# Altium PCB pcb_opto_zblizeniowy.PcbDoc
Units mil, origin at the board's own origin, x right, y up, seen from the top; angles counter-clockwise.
Board outline 2160 x 480 mil, 2 copper layers (Top Layer, Bottom Layer); 11 components, 8 nets, 34 pads, 0 vias.
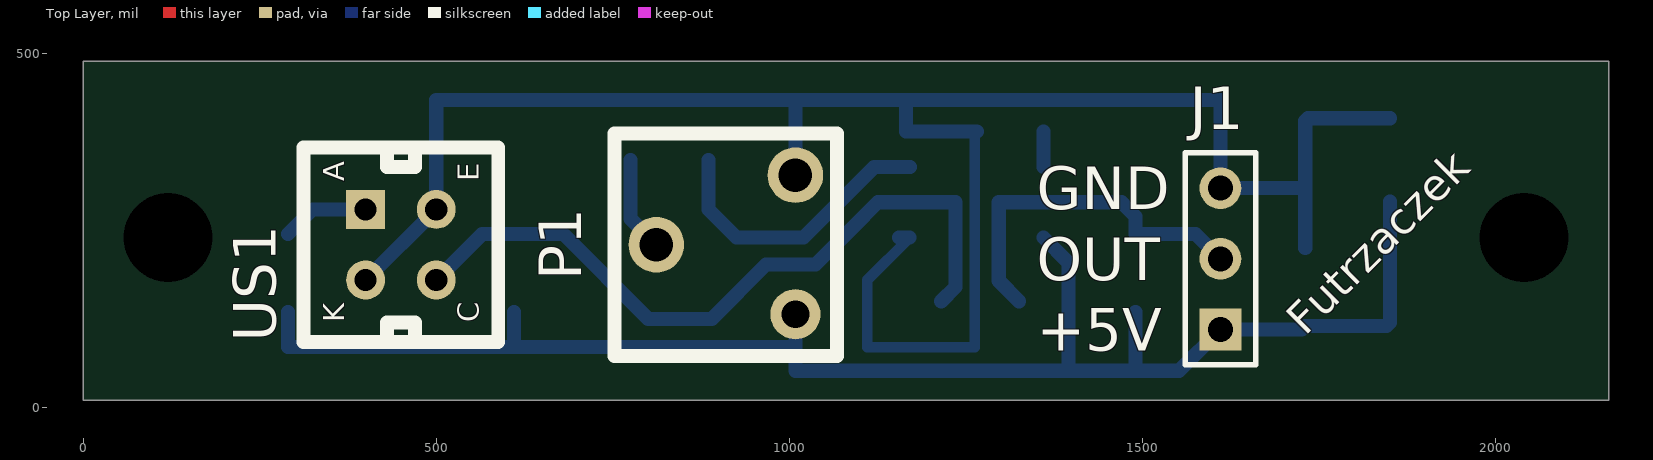
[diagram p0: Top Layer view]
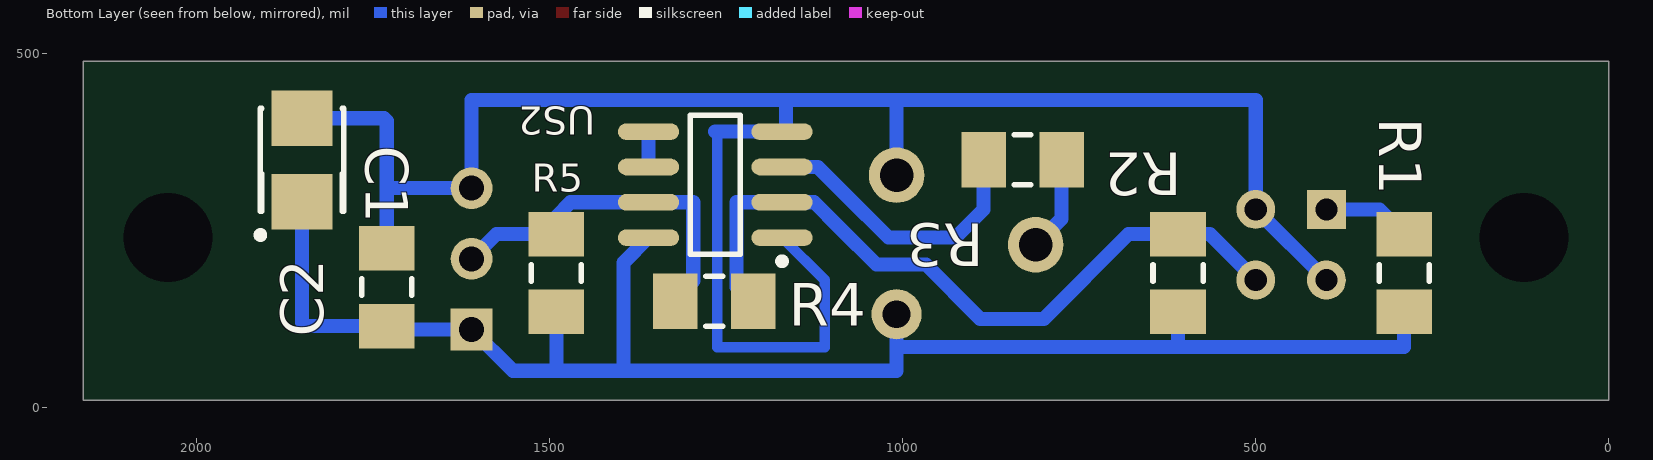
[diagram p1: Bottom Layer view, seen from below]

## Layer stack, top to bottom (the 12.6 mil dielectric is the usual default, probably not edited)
Top Layer: signal copper 1.4
Dielectric: dielectric 12.6, FR-4, Dk 4.8
Bottom Layer: signal copper 1.4

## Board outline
0,10 0,490 2160,490 2160,10

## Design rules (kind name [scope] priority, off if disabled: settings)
Clearance [All] p1: gap=10
PolygonConnect [All] p1: connectstyle=Relief reliefconductorwidth=10 reliefentries=4 polygonreliefangle="90 Angle"
RoutingVias [All] p1: holewidth=28 width=50 viastyle="Through Hole" minholewidth=28 minwidth=50 maxholewidth=28 maxwidth=50
SilkscreenOverComponentPads [All] p1: minsilkscreentomaskgap=10
SolderMaskExpansion [All] p1: expansion=4
Width [All] p1: maxlimit=50 minlimit=15 preferedwidth=50
27 further rules are at their usual default settings.

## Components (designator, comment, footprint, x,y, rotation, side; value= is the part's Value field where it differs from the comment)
C1 "100n" MELF-1206 1730,170 r270 bottom
C2 "22uF/16V B" "Tantal B 3528-1411" 1850,350 r90 bottom
J1 "Header 3" HDR1X3 1610,110 r90 top
P1 "10k" "pot mont poziom" 910,230 r90 top
R1 "220" MELF-1206 290,190 r270 bottom
R2 "4,7k" MELF-1206 610,190 r270 bottom
R3 "4,7k" MELF-1206 830,350 r180 bottom
R4 "470k" MELF-1206 1266.38,150 r180 bottom
R5 "4,7k" MELF-1206 1490,190 r90 bottom
US1 "CNY70" CNY70 450,230 r90 top
US2 "LM311" M08A_N 1265,315 r0 bottom

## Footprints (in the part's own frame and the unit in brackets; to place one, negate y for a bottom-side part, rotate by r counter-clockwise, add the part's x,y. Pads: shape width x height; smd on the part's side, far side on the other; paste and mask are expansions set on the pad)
CNY70 [mm]
  rect 1.4x1.4 hole 0.8: 1(1.27,1.27)
  round 1.4 hole 0.8: 2(-1.27,1.27) 3(-1.27,-1.27) 4(1.27,-1.27)
  silkscreen extent -3.5,-3.5 3.5,3.5
HDR1X3 [mm] "Connector; Header; 3 Position"
  rect 1.5x1.5 hole 0.9: 1(0,0)
  round 1.5 hole 0.9: 2(2.54,0) 3(5.08,0)
  silkscreen extent -1.27,-1.27 6.35,1.27
M08A_N [mm] "SOIC, 8-Leads, Body 4.9x3.9mm, Pitch 1.27mm, IPC Medium Density"
  oval 2.2x0.6 smd: 1(-2.4,1.905) 2(-2.4,0.635) 3(-2.4,-0.635) 4(-2.4,-1.905) 5(2.4,-1.905) 6(2.4,-0.635) 7(2.4,0.635) 8(2.4,1.905)
  silkscreen extent -2.52,-2.5 0.9,2.88, body extent -2,-2.5 2,2.5, height 1.75
MELF-1206 [mm] "Metal Electrode Face (MELF) Resistor; Body 3.2 x 1.8 mm (LxDia)"
  rect 1.6x2 smd: 1(-1.4,0) 2(1.4,0)
  silkscreen extent -0.3,-0.9 0.3,0.9, body extent -2.3,-1.1 2.3,1.1, height 1.85
"pot mont poziom" [mm]
  round 1.8 hole 1: a(-2.5,-2.5)
  round 2 hole 1.2: b(2.5,-2.5) c(0,2.5)
  silkscreen extent -4,-4 4,4
"Tantal B 3528-1411" [mm] "Capacitor, SM Tantalum; Body 3.5 x 2.8 mm (LxW typ)"
  rect 2x2.2 smd: 1(-1.5,0) 2(1.5,0)
  silkscreen extent -2.82,-1.5 1.85,1.63, body extent -2.6,-1.2 2.6,1.2, height 2.5

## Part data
C1: library part kondensator
C2: library part "kond biegunowy", "Polarized Capacitor"
J1: "Header, 3-Pin"
P1: library part "pot mont"
R1 R2 R3 R4 R5: library part rezystor
US2: library part LM311MX, "Voltage Comparator"

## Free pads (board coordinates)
  round 0 hole 125.98: 0(120,240) 1(2040,240)

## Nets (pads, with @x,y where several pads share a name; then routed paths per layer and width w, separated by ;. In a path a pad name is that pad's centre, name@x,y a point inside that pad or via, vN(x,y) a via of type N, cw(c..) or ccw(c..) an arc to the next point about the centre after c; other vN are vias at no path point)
+5V: C1.2 C2.1 J1.1 P1.a R1.2 R2.2 R5.1 US2.8 | length 2250.9
  Bottom Layer w20: R1.2 290,85 610,85 ; R2.2 610,85 ; 755,85 730,85 ; P1.a 1008.43,84.09 ; US2.8 1395,204.49 1395,51.57 ; R5.1 1490,51.57 ; C2.1 1850,120 1844.88,114.88 C1.2 1725.12,110 J1.1 1551.57,51.57 1490,51.57 ; 610,85 730,85 ; 730,85 1007.52,85 1008.43,84.09 ; 1008.43,84.09 1008.43,51.57 1094.53,51.57 1395,51.57 ; 1395,51.57 1490,51.57
GND: C1.1 C2.2 J1.3 P1.b US1.2 US1.4 US2.1 US2.4 | length 2856.4
  Bottom Layer w15: US2.1@1170,240 1110,180 1110,85 1164.39,85 1262.5,85 1262.5,387.5 1265,390
  Bottom Layer w20: US1.2 US1.4 500,435 1130,435 1165,435 ; P1.b 1008.43,433.43 ; US2.1@1155,240 US2.1@1170,240 ; 1265,390 US2.4 1165,390 1165,435 ; C1.1 1730,310 ; C2.2 1734.06,409.06 1730,405 1730,310 ; 1165,435 1610,435 J1.3 1730,310
NetJ1_2: J1.2 R4.1 R5.2 US2.7 | length 513.5
  Bottom Layer w20: R4.1@1325.12,150 1296.18,178.94 1296.18,253.18 1296.18,290 US2.7 1470,290 1490,270 R5.2 1574.88,245.12 J1.2
NetP1_c: P1.c R3.2 | length 135.2
  Bottom Layer w20: R3.2 774.88,266.69 P1.c
NetR1_1: R1.1 US1.1 | length 124.4
  Bottom Layer w20: R1.1 324.88,280 US1.1
NetR2_1: R2.1 R4.2 US1.3 US2.2 | length 1028.8
  Bottom Layer w20: US1.3 565.12,245.12 679.88,245.12 800,125 890,125 966.89,201.89 1036.89,201.89 1088.18,253.18 1125.28,290.28 1125.28,290 1144.03,290 US2.2 1235,290 1235,170.12 R4.2@1214.88,150
NetR3_1: R3.1 US2.3 | length 413.5
  Bottom Layer w20: R3.1 885.12,279.88 925,240 1020,240 1080,300 1120,340 US2.3
NetUS2_5: US2.5 US2.6 | length 50
  Bottom Layer w20: US2.6 US2.5

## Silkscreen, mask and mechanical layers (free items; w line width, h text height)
Top Overlay:
  text "GND" at 1350,280 h60
  text "OUT" at 1350,180 h60
  text "Futrzaczek" at 1730,100 h45 r45
  text "+5V" at 1350,80 h60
